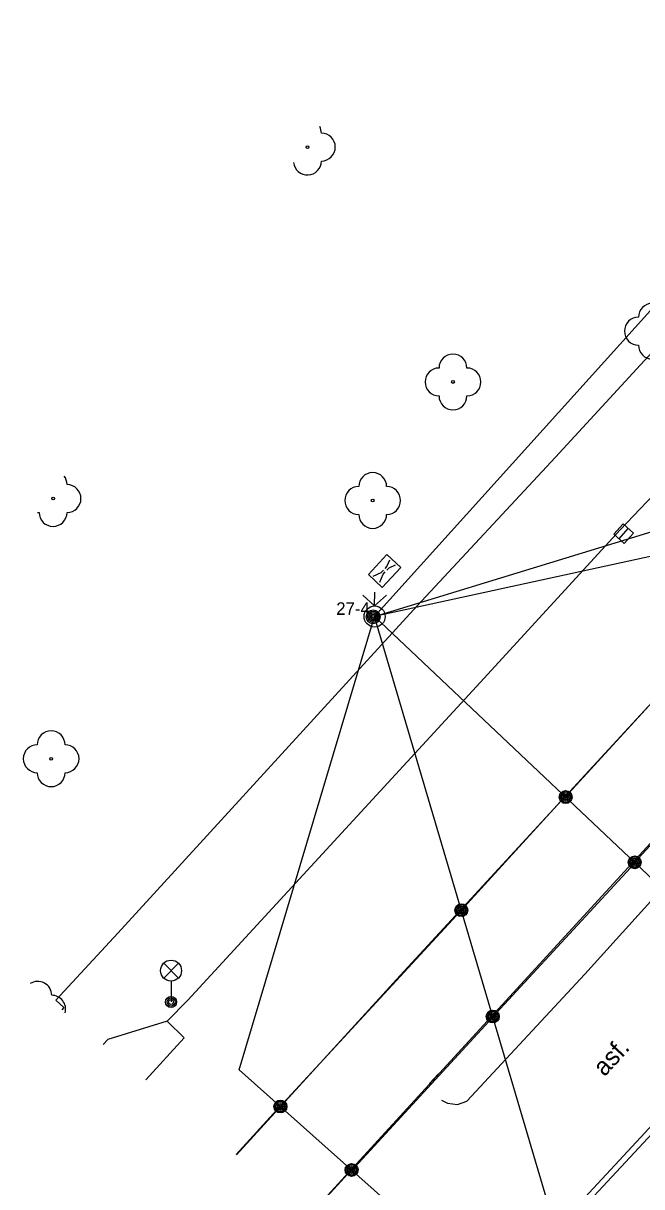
# Model space of a CAD drawing. Extents: x -598168 to -598014, y -1160410 to -1160294.
# Drawn here: x -598167.91 to -598145.73, y -1160385.83 to -1160344.12 of the extents above; entities that cross this region are included whole.
import ezdxf

# ---------------------------------------------------------------- set-up
doc = ezdxf.new("R2010")
doc.units = 0
for name, color, linetype in [('Kabelové vedení_Kabely', 7, 'Continuous'), ('Level 10', 7, 'Continuous'), ('Level 11', 7, 'Continuous'), ('Level 13', 7, 'Continuous'), ('Level 22', 7, 'Continuous'), ('Level 25', 7, 'Continuous'), ('Level 27', 7, 'Continuous'), ('Level 33', 7, 'Continuous'), ('Level 40', 7, 'Continuous'), ('Trolejové vedení_Kotvení', 7, 'Continuous'), ('Trolejové vedení_Nosné lano', 7, 'Continuous'), ('Trolejové vedení_Stožáry', 7, 'Continuous'), ('Trolejové vedení_Trolejový drát', 7, 'Continuous'), ('Trolejové vedení_Zavěšení', 7, 'Continuous')]:
    doc.layers.add(name, color=color, linetype=linetype)

# ---------------------------------------------------------------- blocks, each defined once
blk = doc.blocks.new('TRAKCN')
at = {"layer": 'Trolejové vedení_Stožáry'}
for points in [[(-0.0008, 0.0382), (0.0004, 0.0868)], [(0, 0.0382), (-0.042, 0.0763)], [(0, 0.0386), (0.0421, 0.0768)]]:
    blk.add_lwpolyline(points, dxfattribs=at)
blk.add_circle((0, 0), 0.0378, dxfattribs=at)
blk = doc.blocks.new('ZAVES1')
at = {"layer": 'Trolejové vedení_Zavěšení'}
for points in [[(0, 0), (-0.0035, 0.0035)], [(0, 0), (-0.0035, -0.0035)], [(0, 0), (0.0035, 0.0035)], [(0, 0), (0.0035, -0.0035)]]:
    blk.add_lwpolyline(points, dxfattribs=at)
for radius in [0.0231, 0.0194, 0.0147, 0.00975, 0.00529]:
    blk.add_circle((0, 0), radius, dxfattribs=at)
blk = doc.blocks.new('KOTVEN')
at = {"layer": 'Trolejové vedení_Kotvení'}
blk.add_lwpolyline([(-0.0343, 0.0522), (0.0333, 0.0522), (0.0338, -0.0458), (-0.0343, -0.0455)], close=True, dxfattribs=at)
for points in [[(-0.0158, 0.0443), (-0.0041, 0.0154), (-0.004, 0.0041)], [(0.0172, 0.0445), (0.005, 0.0158), (0.005, 0.0039)], [(-0.0145, -0.0376), (-0.0045, -0.015), (-0.0045, -0.004)], [(0.0131, -0.0362), (0.0052, -0.0148), (0.0051, -0.004)]]:
    blk.add_lwpolyline(points, dxfattribs=at)

msp = doc.modelspace()

# ---------------------------------------------------------------- linework, layer by layer
at = {"layer": 'Kabelové vedení_Kabely'}
for points in [[(-598152.91, -1160382.733), (-598152.7, -1160382.84), (-598152.34, -1160382.89), (-598152, -1160382.77), (-598147.77, -1160378.21), (-598139.11, -1160368.63), (-598136.37, -1160365.51)], [(-598153.02, -1160381.79), (-598153.348, -1160382.135)]]:
    msp.add_lwpolyline(points, dxfattribs=at)
at = {"layer": 'Level 10'}
for points in [[(-598146.51, -1160362.28), (-598144.82, -1160360.51), (-598130.04, -1160344.19)], [(-598162.01, -1160379.14), (-598151.53, -1160367.75), (-598146.51, -1160362.28)], [(-598133.2, -1160370.72), (-598138.12, -1160376.03), (-598144.39, -1160382.88), (-598151.47, -1160390.49)], [(-598162.01, -1160379.14), (-598162.75, -1160379.9)], [(-598162.75, -1160379.9), (-598164.88, -1160380.56), (-598165.039, -1160380.732)]]:
    msp.add_lwpolyline(points, dxfattribs=at)
at = {"layer": 'Level 11'}
for points in [[(-598132.25, -1160340.71), (-598132.95, -1160342), (-598133.57, -1160342.97), (-598134.35, -1160343.93), (-598135.38, -1160345.07), (-598148.83, -1160359.68)], [(-598164.52, -1160376.74), (-598153.78, -1160365.01), (-598148.83, -1160359.68)], [(-598133.34, -1160370.58), (-598138.27, -1160375.9), (-598144.54, -1160382.74), (-598151.61, -1160390.36)], [(-598164.52, -1160376.74), (-598166.74, -1160379.15), (-598166.45, -1160379.41), (-598166.528, -1160379.497)], [(-598163.518, -1160381.995), (-598162.14, -1160380.5), (-598162.75, -1160379.9)]]:
    msp.add_lwpolyline(points, dxfattribs=at)
at = {"layer": 'Level 13'}
for points in [[(-598140.7, -1160363.4), (-598154.39, -1160378.26), (-598160.268, -1160384.692)], [(-598138.52, -1160366), (-598151.93, -1160380.62), (-598157.652, -1160386.863)]]:
    msp.add_lwpolyline(points, dxfattribs=at)
at = {"layer": 'Level 22'}
for centre in [(-598157.72, -1160348.56), (-598152.5, -1160356.98), (-598166.84, -1160361.16), (-598155.38, -1160361.23), (-598166.91, -1160370.49)]:
    msp.add_circle(centre, 0.05, dxfattribs=at)
for centre, start, end in [((-598157.72, -1160348.06), 0, 28.0812), ((-598157.22, -1160348.56), 270, 90), ((-598157.72, -1160349.06), 185.5043, 0), ((-598145.35, -1160354.66), 0, 180), ((-598145.85, -1160355.16), 90, 270), ((-598152.5, -1160356.48), 0, 180), ((-598145.35, -1160355.66), 180, 0), ((-598153, -1160356.98), 90, 270), ((-598152, -1160356.98), 270, 90), ((-598152.5, -1160357.48), 180, 0), ((-598166.84, -1160360.66), 0, 37.7516), ((-598155.38, -1160360.73), 0, 180), ((-598166.34, -1160361.16), 270, 90), ((-598155.88, -1160361.23), 90, 270), ((-598154.88, -1160361.23), 270, 90), ((-598167.34, -1160361.16), 263.3697, 270), ((-598166.84, -1160361.66), 180, 0), ((-598155.38, -1160361.73), 180, 0), ((-598166.91, -1160369.99), 0, 180), ((-598167.41, -1160370.49), 90, 270), ((-598166.41, -1160370.49), 270, 90), ((-598166.91, -1160370.99), 180, 0), ((-598167.39, -1160378.97), 0, 123.4617), ((-598166.89, -1160379.47), 345.1898, 90)]:
    msp.add_arc(centre, 0.5, start, end, dxfattribs=at)
at = {"layer": 'Level 25'}
for radius in [0.25, 0.2, 0.15, 0.1, 0.05]:
    msp.add_circle((-598155.36, -1160365.4), radius, dxfattribs=at)
at = {"layer": 'Level 27'}
msp.add_line((-598146.546, -1160362.607), (-598146.214, -1160362.233), dxfattribs=at)
msp.add_lwpolyline([(-598146.358, -1160362.773), (-598146.027, -1160362.398), (-598146.402, -1160362.067), (-598146.733, -1160362.442)], close=True, dxfattribs=at)
at = {"layer": 'Level 33'}
for p, q in [((-598162.875, -1160378.35), (-598162.345, -1160377.82)), ((-598162.875, -1160377.82), (-598162.345, -1160378.35)), ((-598162.61, -1160378.46), (-598162.61, -1160379.21))]:
    msp.add_line(p, q, dxfattribs=at)
for centre, radius in [((-598162.61, -1160378.085), 0.375), ((-598162.61, -1160379.21), 0.2), ((-598162.61, -1160379.21), 0.145), ((-598162.61, -1160379.21), 0.0876)]:
    msp.add_circle(centre, radius, dxfattribs=at)
at = {"layer": 'Trolejové vedení_Nosné lano'}
for points in [[(-598155.31, -1160365.39), (-598139.37, -1160347.71)], [(-598155.31, -1160365.39), (-598139.37, -1160347.71)], [(-598155.31, -1160365.39), (-598141.57, -1160361.18)], [(-598155.31, -1160365.39), (-598141.57, -1160361.18)], [(-598140.75, -1160362.22), (-598155.31, -1160365.39)], [(-598140.75, -1160362.22), (-598155.31, -1160365.39)], [(-598160.17, -1160381.64), (-598155.31, -1160365.39)], [(-598160.17, -1160381.64), (-598155.31, -1160365.39)], [(-598139.85, -1160380), (-598155.31, -1160365.39)], [(-598148.32, -1160389.04), (-598155.31, -1160365.39)], [(-598139.85, -1160380), (-598155.31, -1160365.39)], [(-598148.32, -1160389.04), (-598155.31, -1160365.39)], [(-598149.93, -1160390.76), (-598160.17, -1160381.64)], [(-598149.93, -1160390.76), (-598160.17, -1160381.64)]]:
    msp.add_lwpolyline(points, dxfattribs=at)
at = {"layer": 'Trolejové vedení_Trolejový drát'}
for points in [[(-598148.482, -1160371.872), (-598140.232, -1160362.87)], [(-598145.996, -1160374.213), (-598138.095, -1160365.626)], [(-598152.228, -1160375.954), (-598148.513, -1160371.876)], [(-598151.1, -1160379.763), (-598145.992, -1160374.244)], [(-598158.721, -1160382.975), (-598152.228, -1160375.954)], [(-598156.147, -1160385.275), (-598151.07, -1160379.759)], [(-598160.279, -1160384.683), (-598158.694, -1160382.941)], [(-598157.642, -1160386.872), (-598156.151, -1160385.245)]]:
    msp.add_lwpolyline(points, dxfattribs=at)

# ---------------------------------------------------------------- block references
at = {"layer": 'Trolejové vedení_Kotvení', "xscale": 10, "yscale": 10, "rotation": 137.1400661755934}
msp.add_blockref('KOTVEN', (-598154.932, -1160363.73), dxfattribs=at)
at = {"layer": 'Trolejové vedení_Stožáry', "xscale": 10, "yscale": 10}
msp.add_blockref('TRAKCN', (-598155.31, -1160365.39), dxfattribs=at)
at = {"layer": 'Trolejové vedení_Zavěšení', "xscale": 10, "yscale": 10}
for p in [(-598148.46, -1160371.863), (-598145.985, -1160374.202), (-598152.2, -1160375.919), (-598151.074, -1160379.731), (-598158.689, -1160382.959), (-598156.137, -1160385.233)]:
    msp.add_blockref('ZAVES1', p, dxfattribs=at)

# ---------------------------------------------------------------- texts
at = {"layer": 'Level 40'}
msp.add_text(' asf.', height=0.65, rotation=47.53, dxfattribs=at).set_placement((-598147.23, -1160382.09))
at = {"layer": 'Trolejové vedení_Stožáry'}
msp.add_text('27-4', height=0.45, dxfattribs=at).set_placement((-598156.687, -1160365.33))

doc.saveas('drawing.dxf')
